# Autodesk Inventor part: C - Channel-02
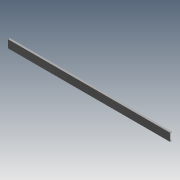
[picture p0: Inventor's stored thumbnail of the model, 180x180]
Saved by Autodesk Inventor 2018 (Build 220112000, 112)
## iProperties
Created: 2018-02
Part Number: C - Channel-02
Material: Steel, Mild
Document SubType Name: Modeling
Designer: STK
Mass: 474202 g
Surface Area: 86052.5 cm^2
Volume: 60407.9 cm^3
Density: 7.85 g/cm^3
Appearance: Semi-Polished
Author: STK
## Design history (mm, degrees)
derived "C - Channel.ipt"
feature "Solid1::C - Channel.ipt"
tag "TaggingFeature1"
body "Solid1"
other parameters: "d0" = 381, "d1" = 12.7, "d2" = 16.1544, "d3" = 92.075, "d4" = 7833.2584, "d5" = 0, "d6" = 158.75, "d8" = 0, "d9" = 6.35, "d11" = 0
